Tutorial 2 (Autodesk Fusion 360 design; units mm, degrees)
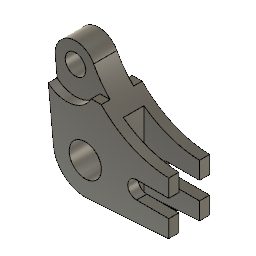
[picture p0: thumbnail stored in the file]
sketch "Sketch1" plane through (0, 0, 0) normal (0, 1, 0) x axis (1, 0, 0)
  line L1 (0, 0) -> (0, -77.8796)
  line L2 (57, 18) -> (1.5614, 21.9445)
  line L3 (57, 6) -> (57, 18)
  line L4 (57, -18) -> (57, -6)
  line L5 (57, -6) -> (35, -6)
  line L6 (60.4494, 0) -> (0, 0)
  line L7 (35, 6) -> (57, 6)
  line L8 (-22.8462, -85.2632) -> (0, 0)
  line L9 (-21.8949, 2.1482) -> (-26.6152, -45.9633)
  arc A1 centre (0, 0) radius 22 clockwise from (-21.8949, 2.1482) to (1.5614, 21.9445)
  arc A2 centre (59.0419, -84.9689) radius 67 clockwise from (-0.2854, -53.8358) to (57, -18)
  arc A3 centre (35, 0) radius 6 clockwise from (35, -6) to (35, 6)
  arc A4 centre (-12.6821, -47.3304) radius 14 clockwise from (0, -53.2602) to (-26.6152, -45.9633)
  circle C1 centre (0, 0) radius 11
  circle C2 centre (-12.6821, -47.3304) radius 7
  point P2 (0, 0)
  point P19 (0, 0)
  point P23 (0, 0)
  point P25 (0, 0)
  point P21 (-12.6821, -47.3304)
  point P24 (-0.2854, -53.8358)
  point P20 (35, 0)
  point P15 (0, -53.2602)
  point P16 (0, 0)
  point P22 (0, 0)
  point P1 (0, 0)
  point P3 (57, 18)
  point P4 (57, -18)
  coincident P2 P19
  coincident P19 P23
  vertical L1
  perpendicular L1 L6
  coincident P2 P25
  coincident P21 L8
  perpendicular L3 L6
  perpendicular L3 L7
  tangent A3 L7
  tangent L5 A3
  perpendicular L3 L5
  perpendicular L4 L6
  tangent L2 A1
  collinear L3 L4
  equal L3 L4
  coincident P24 A4
  tangent A2 A4
  coincident P20 L6
  tangent A4 L9
  tangent A1 L9
  coincident P15 L1
  concentric A4 C2
  coincident P16 P22
  coincident P1 P22
  coincident P1 P2
  dimension "d1" radius A1 = 22
  dimension "d2" angle L1 L8 = 15
  dimension "d3" radius A4 = 14
  dimension "d4" distance P21 P22 = 49
  dimension "d5" radius A2 = 67
  dimension "d6" distance P19 L3 = 57
  dimension "d7" distance P20 L3 = 22
  dimension "d8" distance P3 P4 = 36
  dimension "d9" radius A3 = 6
  dimension "d10" diameter C2 = 14
  dimension "d11" diameter C1 = 22
extrude "Extrude1" new body sketch "Sketch1" profile of L2 L3 A1 L4 A2 L5 A3 L7 A4 L9 C1 C2 distance 28
sketch "Sketch3" plane through (0, -14, 0) normal (0, -1, 0) x axis (1, 0, 0)
  line L1 (57, -18) -> (1.5614, -21.9445)
  line L2 (57, -6) -> (57, -18)
  line L3 (35, -6) -> (57, -6)
  line L4 (57, 6) -> (35, 6)
  line L5 (57, 18) -> (57, 6)
  line L6 (-21.8949, -2.1482) -> (-26.6152, 45.9633)
  line L7 (-21.8949, -2.1482) -> (-26.6152, 45.9633)
  line L8 (10.9395, 38.3304) -> (4.0511, 38.3304)
  circle C1 centre (-12.6821, 47.3304) radius 7
  circle C2 centre (0, 0) radius 11
  arc A1 centre (0, 0) radius 22 clockwise from (1.5614, -21.9445) to (-21.8949, -2.1482)
  arc A2 centre (35, 0) radius 6 clockwise from (35, -6) to (35, 6)
  arc A3 centre (59.0419, 84.9689) radius 67 clockwise from (57, 18) to (-0.2854, 53.8358)
  arc A4 centre (-12.6821, 47.3304) radius 14 clockwise from (-26.6152, 45.9633) to (-0.2854, 53.8358)
  arc A5 centre (-12.6821, 47.3304) radius 14 clockwise from (-26.6152, 45.9633) to (-0.2854, 53.8358)
  arc A6 centre (59.0419, 84.9689) radius 67 clockwise from (57, 18) to (-0.2854, 53.8358)
  arc A7 centre (-12.6821, 47.3304) radius 19 clockwise from (4.0511, 38.3304) to (-25.361, 33.1795)
  point P25 (-25.361, 33.1795)
  point P26 (10.9395, 38.3304)
  point P23 (-12.6821, 47.3304)
  concentric A5 A7
  horizontal L8
  coincident L6 P25
  coincident A3 P26
  dimension "d16" radius A7 = 19
  dimension "d17" distance P23 L8 = 9
extrude "Extrude2" cut sketch "Sketch3" profile of C1 A3 A4 L6 L7 A5 A6 A7 L8 against normal blind 6
mirror "Mirror1"
sketch "Sketch4" plane through (57, 0, 0) normal (1, 0, 0) x axis (0, 1, 0)
  line L1 (14, -18) -> (-14, -18)
  line L2 (14, -6) -> (14, -18)
  line L3 (-14, -6) -> (14, -6)
  line L4 (-14, -18) -> (-14, -6)
  line L5 (0, 67.9123) -> (0, 0)
  line L6 (7, -21.9445) -> (-7, -21.9445)
  line L7 (7, 38.3304) -> (7, -21.9445)
  line L8 (-7, 38.3304) -> (7, 38.3304)
  line L9 (-7, -21.9445) -> (-7, 38.3304)
  line L10 (-14, -21.9445) -> (14, -21.9445)
  line L11 (8, 38.3304) -> (14, 38.3304)
  point P1 (0, 0)
  point P6 (0, 0)
  point P8 (-7, -21.9445)
  coincident P1 P6
  perpendicular L3 L5
  horizontal L6
  vertical L7
  horizontal L8
  vertical L9
  coincident P8 L10
  symmetric L5 L7 L9
  collinear L8 L11
  dimension "d21" distance L7 L9 = 14
extrude "Extrude3" cut sketch "Sketch4" profile of L1 L3 L6 L7 L8 L9 L10 against normal blind 38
